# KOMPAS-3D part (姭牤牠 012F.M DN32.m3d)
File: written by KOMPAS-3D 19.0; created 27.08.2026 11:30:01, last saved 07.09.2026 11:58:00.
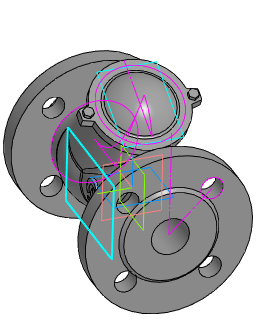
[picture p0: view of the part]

Document properties: Автор: Энергия; Полное имя файла: Z:\3.Личные\kachalov\001_3d для проектировщиков\х.х Тип 012F\012F.M\Клапан 012F.M DN32.m3d

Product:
- Part/product: (unnamed)  | designation Клапан 012F.M DN32
    Масса: 9.54874

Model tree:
1. Эскиз:1
2. Элемент вращения:1
     Угол 1 = 360
3. Эскиз:2  (with: Элемент вращения:1)
4. Перпендикулярная плоскость:1
5. Эскиз:3
6. Эскиз:12  (with: Элемент вращения:1)
7. Элемент по сечениям:1
8. Эскиз:7
9. Элемент выдавливания:2
     Расстояние 2 = 8
10. Эскиз:9  (with: Элемент выдавливания:2)
11. Элемент вращения:2  (with: Элемент выдавливания:2)
     Угол 1 = 360
12. Эскиз:10  (with: Элемент вращения:1)
13. Элемент выдавливания:3  (with: Элемент вращения:1)
     Расстояние 2 = 16
14. Массив по концентрической сетке:1  (with: Элемент выдавливания:3, Эскиз:10, Элемент вращения:1)  (4 pattern instances)
     Шаг 2 = 360
15. Эскиз:11  (with: Элемент вращения:1)
16. Элемент выдавливания:4  (with: Элемент вращения:1)
     Расстояние 2 = 16
17. Массив по концентрической сетке:2  (with: Элемент выдавливания:4, Эскиз:11, Элемент вращения:1)  (4 pattern instances)
     Шаг 2 = 360
18. Скругление:6  (with: Элемент вращения:2)
     Радиус = 3
19. Эскиз:13  (with: Элемент выдавливания:2, Скругление:6)
20. Элемент выдавливания:5  (with: Элемент выдавливания:2)
     Расстояние 1 = 3.5; Расстояние 2 = 11.5; Смещение 2 = 3.5
21. Зеркальный массив:3
22. Экземпляр ( 1 )
23. Экземпляр ( 2 )  (with: Элемент выдавливания:5)
24. Касательная плоскость:1  (with: Элемент вращения:1)
     Угол = 90
25. Смещенная плоскость:1
     Расстояние = 1
26. Эскиз:14
27. Элемент выдавливания:6  (with: Элемент вращения:1)
     Расстояние 1 = -1.00064; Расстояние 2 = 1
28. Эскиз:15  (with: Элемент вращения:1)
29. Элемент вращения:3
     Угол 1 = 360
30. Скругление:10  (with: Элемент вращения:3, Элемент по сечениям:1)
     Радиус = 5
31. Эскиз:16
32. Элемент выдавливания:7
     Расстояние 1 = 45
33. Эскиз:17  (with: Элемент выдавливания:7)
34. Элемент выдавливания:8
     Расстояние 1 = 6.5
35. Эскиз:18  (with: Элемент вращения:1)
36. Элемент выдавливания:9
     Расстояние 2 = 180

Expressions: Dn/2; D/2; D2/2; D2/2-5; 360/(2*n); 360/(n*2); D2-6; D2-5; D2+5; (D2+5)/2
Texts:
  Клапан 012F.M DN32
